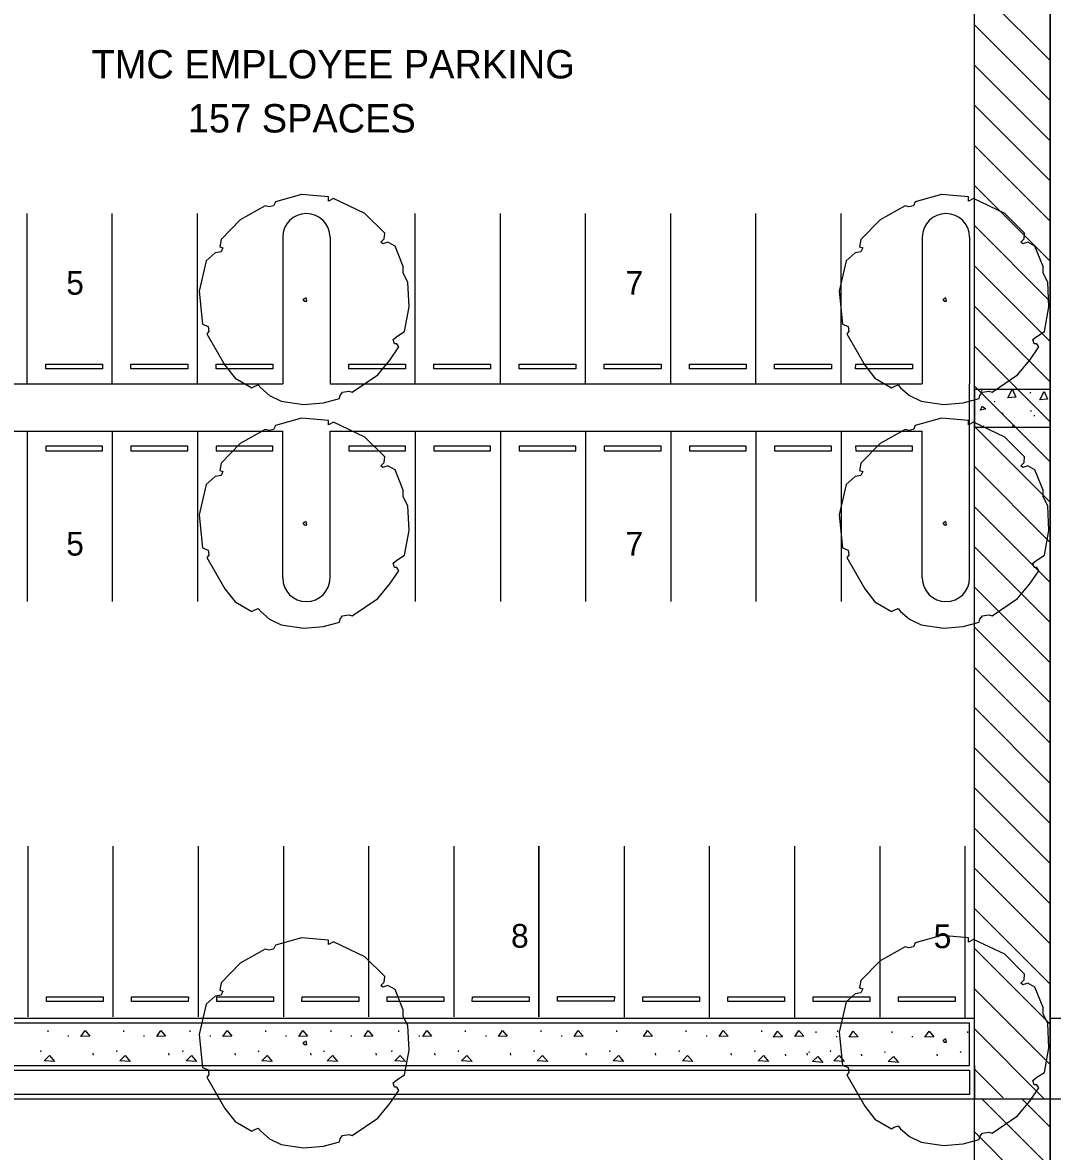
# Model space of a CAD drawing. Extents: x 6712138 to 6712574, y 1869536 to 1870160.
# Drawn here: x 6712370.5 to 6712479.3, y 1869919.6 to 1870038.8 of the extents above; entities that cross this region are included whole.
import ezdxf

# ---------------------------------------------------------------- set-up
doc = ezdxf.new("R2010")
doc.units = 0
for name, color, linetype in [('A-ANNO-TEXT', 7, 'Continuous'), ('A-FLOR-CASE', 7, 'Continuous'), ('A-FLOR-PATT', 7, 'Continuous'), ('A-WALL-MBNI', 7, 'Continuous'), ('C-PRKG-CONC', 7, 'Continuous'), ('C-PRKG-STRP', 7, 'Continuous'), ('L-tree', 7, 'Continuous')]:
    doc.layers.add(name, color=color, linetype=linetype)

# ---------------------------------------------------------------- blocks, each defined once
blk = doc.blocks.new('TREE 1')
at = {"layer": 'L-tree'}
for p, q in [((-0.0275, 0.572), (-0.1682, 0.5324)), ((0.1167, 0.5588), (-0.0275, 0.572)), ((0.1167, 0.5368), (0.1167, 0.5588)), ((0.1441, 0.55), (0.1167, 0.5368)), ((0.3123, 0.4708), (0.1441, 0.55)), ((-0.2231, 0.5104), (-0.357, 0.4356)), ((-0.2025, 0.506), (-0.2231, 0.5104)), ((-0.1785, 0.5104), (-0.2025, 0.506)), ((-0.1682, 0.5324), (-0.1785, 0.5104)), ((-0.357, 0.4356), (-0.4599, 0.33)), ((0.4187, 0.3652), (0.3123, 0.4708)), ((0.4153, 0.3344), (0.4187, 0.3652)), ((-0.4599, 0.33), (-0.4668, 0.2904)), ((0.3981, 0.3168), (0.4153, 0.3344)), ((0.4084, 0.308), (0.3981, 0.3168)), ((0.4359, 0.3168), (0.4084, 0.308)), ((0.4737, 0.2948), (0.4359, 0.3168)), ((-0.4908, 0.2596), (-0.5389, 0.2156)), ((-0.4599, 0.264), (-0.4908, 0.2596)), ((-0.4668, 0.2904), (-0.4496, 0.286)), ((-0.4496, 0.286), (-0.4599, 0.264)), ((0.5183, 0.1848), (0.4737, 0.2948)), ((-0.5389, 0.2156), (-0.5766, 0.0528)), ((0.5183, 0.1496), (0.5183, 0.1848)), ((0.5423, 0.1012), (0.5183, 0.1496)), ((0.5492, -0.0308), (0.5423, 0.1012)), ((-0.5766, 0.0528), (-0.5595, -0.1232)), ((-0.0034, 0.0176), (-0.0206, 0.0088)), ((-0.0206, 0.0088), (-0.0137, 0)), ((-0.0137, 0), (0, 0)), ((0, 0), (-0.0034, 0.0176)), ((0.5251, -0.1628), (0.5492, -0.0308)), ((-0.5595, -0.1232), (-0.5286, -0.1364)), ((-0.5251, -0.1628), (-0.5354, -0.176)), ((-0.5354, -0.176), (-0.4393, -0.3432)), ((-0.5286, -0.1364), (-0.5251, -0.1628)), ((0.4839, -0.1892), (0.5251, -0.1628)), ((0.4634, -0.2068), (0.4839, -0.1892)), ((0.4702, -0.2288), (0.4634, -0.2068)), ((0.4839, -0.2288), (0.4702, -0.2288)), ((0.4942, -0.2464), (0.4839, -0.2288)), ((0.4462, -0.3168), (0.4942, -0.2464)), ((-0.4393, -0.3432), (-0.3844, -0.4136)), ((0.381, -0.396), (0.4462, -0.3168)), ((-0.3844, -0.4136), (-0.2952, -0.4664)), ((0.2437, -0.4884), (0.381, -0.396)), ((-0.2952, -0.4664), (-0.2815, -0.4576)), ((-0.2815, -0.4576), (-0.2609, -0.4488)), ((-0.2609, -0.4488), (-0.2471, -0.4664)), ((-0.2471, -0.4664), (-0.1991, -0.506)), ((0.1922, -0.4884), (0.2265, -0.484)), ((0.2265, -0.484), (0.2437, -0.4884)), ((-0.1991, -0.506), (-0.1373, -0.5368)), ((-0.1373, -0.5368), (-0.0172, -0.5544)), ((0.0892, -0.5456), (0.175, -0.5236)), ((0.175, -0.5236), (0.1785, -0.506)), ((0.1785, -0.506), (0.1922, -0.4884)), ((-0.0172, -0.5544), (0.0892, -0.5456))]:
    blk.add_line(p, q, dxfattribs=at)

msp = doc.modelspace()

# ---------------------------------------------------------------- linework, layer by layer
at = {"layer": 'A-FLOR-CASE'}
msp.add_lwpolyline([(6712471.06, 1869725.57), (6712471.06, 1870137.85), (6712479.06, 1870137.85), (6712479.06, 1869725.57)], close=True, dxfattribs=at)
at = {"layer": 'A-FLOR-PATT'}
for p, q in [((6712471.82, 1869999.86), (6712471.89, 1870000.02)), ((6712476.96, 1869999.68), (6712477.02, 1869999.84)), ((6712473.14, 1869998.89), (6712473.2, 1869998.78)), ((6712473.99, 1869997.6), (6712474.06, 1869997.5)), ((6712476.98, 1869997.88), (6712477.05, 1869997.76)), ((6712477.36, 1869997.38), (6712477.43, 1869997.27)), ((6712471.99, 1869996.12), (6712472.06, 1869996.28)), ((6712477.18, 1869996.07), (6712477.19, 1869996.1)), ((6712373.2, 1869932.21), (6712373.2, 1869932.37)), ((6712375.37, 1869931.74), (6712375.37, 1869931.85)), ((6712381.2, 1869932.21), (6712381.2, 1869932.37)), ((6712383.37, 1869931.74), (6712383.37, 1869931.85)), ((6712388.2, 1869932.21), (6712388.2, 1869932.37)), ((6712390.37, 1869931.74), (6712390.37, 1869931.85)), ((6712396.2, 1869932.21), (6712396.2, 1869932.37)), ((6712398.37, 1869931.74), (6712398.37, 1869931.85)), ((6712403.1, 1869932.21), (6712403.1, 1869932.37)), ((6712405.27, 1869931.74), (6712405.27, 1869931.85)), ((6712410.27, 1869932.21), (6712410.27, 1869932.37)), ((6712412.44, 1869931.74), (6712412.44, 1869931.85)), ((6712417.3, 1869932.21), (6712417.3, 1869932.37)), ((6712419.47, 1869931.74), (6712419.47, 1869931.85)), ((6712425.3, 1869932.21), (6712425.3, 1869932.37)), ((6712427.47, 1869931.74), (6712427.47, 1869931.85)), ((6712433.3, 1869932.21), (6712433.3, 1869932.37)), ((6712440.62, 1869932.21), (6712440.62, 1869932.37)), ((6712442.79, 1869931.74), (6712442.79, 1869931.85)), ((6712448.62, 1869932.21), (6712448.62, 1869932.37)), ((6712450.79, 1869931.74), (6712450.79, 1869931.85)), ((6712454.36, 1869932.11), (6712454.36, 1869932.27)), ((6712456.53, 1869931.64), (6712456.53, 1869931.75)), ((6712456.62, 1869932.21), (6712456.62, 1869932.37)), ((6712462.36, 1869932.11), (6712462.36, 1869932.27)), ((6712464.53, 1869931.64), (6712464.53, 1869931.75)), ((6712470.36, 1869932.11), (6712470.36, 1869932.27)), ((6712372.45, 1869930.12), (6712372.49, 1869930.24)), ((6712378, 1869929.77), (6712377.96, 1869929.97)), ((6712380.45, 1869930.12), (6712380.49, 1869930.24)), ((6712386, 1869929.77), (6712385.96, 1869929.97)), ((6712387.45, 1869930.12), (6712387.49, 1869930.24)), ((6712393, 1869929.77), (6712392.96, 1869929.97)), ((6712395.45, 1869930.12), (6712395.49, 1869930.24)), ((6712401, 1869929.77), (6712400.96, 1869929.97)), ((6712402.35, 1869930.12), (6712402.39, 1869930.24)), ((6712407.9, 1869929.77), (6712407.86, 1869929.97)), ((6712409.52, 1869930.12), (6712409.56, 1869930.24)), ((6712414.1, 1869929.77), (6712414.06, 1869929.97)), ((6712416.55, 1869930.12), (6712416.59, 1869930.24)), ((6712422.1, 1869929.77), (6712422.06, 1869929.97)), ((6712424.55, 1869930.12), (6712424.59, 1869930.24)), ((6712430.1, 1869929.77), (6712430.06, 1869929.97)), ((6712432.55, 1869930.12), (6712432.59, 1869930.24)), ((6712437.42, 1869929.77), (6712437.38, 1869929.97)), ((6712439.87, 1869930.12), (6712439.91, 1869930.24)), ((6712445.42, 1869929.77), (6712445.38, 1869929.97)), ((6712447.87, 1869930.12), (6712447.91, 1869930.24)), ((6712451.16, 1869929.67), (6712451.12, 1869929.87)), ((6712453.42, 1869929.77), (6712453.38, 1869929.97)), ((6712453.61, 1869930.02), (6712453.65, 1869930.14)), ((6712455.87, 1869930.12), (6712455.91, 1869930.24)), ((6712459.16, 1869929.67), (6712459.12, 1869929.87)), ((6712461.61, 1869930.02), (6712461.65, 1869930.14)), ((6712467.16, 1869929.67), (6712467.12, 1869929.87)), ((6712469.61, 1869930.02), (6712469.65, 1869930.14))]:
    msp.add_line(p, q, dxfattribs=at)
for points in [[(6712474.59, 1869999.2), (6712475.05, 1870000.07)], [(6712475.08, 1870000.07), (6712475.43, 1869999.28), (6712474.61, 1869999.2)], [(6712477.96, 1869998.98), (6712478.43, 1869999.88), (6712478.8, 1869999.05), (6712477.98, 1869998.98)], [(6712471.7, 1869997.88), (6712471.9, 1869998.32), (6712472.26, 1869998.05), (6712471.7, 1869997.88)], [(6712475.07, 1869996.07), (6712475.23, 1869996.36), (6712475.36, 1869996.07)], [(6712478.57, 1869996.07), (6712478.6, 1869996.14), (6712478.63, 1869996.07)]]:
    msp.add_lwpolyline(points, dxfattribs=at)
for points in [[(6712376.68, 1869931.74), (6712377.11, 1869932.37), (6712377.62, 1869931.78)], [(6712384.68, 1869931.74), (6712385.11, 1869932.37), (6712385.62, 1869931.78)], [(6712391.68, 1869931.74), (6712392.11, 1869932.37), (6712392.62, 1869931.78)], [(6712399.68, 1869931.74), (6712400.11, 1869932.37), (6712400.62, 1869931.78)], [(6712406.58, 1869931.74), (6712407.01, 1869932.37), (6712407.52, 1869931.78)], [(6712412.78, 1869931.74), (6712413.21, 1869932.37), (6712413.72, 1869931.78)], [(6712420.78, 1869931.74), (6712421.21, 1869932.37), (6712421.72, 1869931.78)], [(6712428.78, 1869931.74), (6712429.21, 1869932.37), (6712429.72, 1869931.78)], [(6712436.1, 1869931.74), (6712436.53, 1869932.37), (6712437.04, 1869931.78)], [(6712444.1, 1869931.74), (6712444.53, 1869932.37), (6712445.04, 1869931.78)], [(6712449.84, 1869931.65), (6712450.27, 1869932.28), (6712450.78, 1869931.69)], [(6712452.1, 1869931.74), (6712452.53, 1869932.37), (6712453.04, 1869931.78)], [(6712457.84, 1869931.65), (6712458.27, 1869932.28), (6712458.78, 1869931.69)], [(6712465.84, 1869931.65), (6712466.27, 1869932.28), (6712466.78, 1869931.69)], [(6712372.79, 1869929.16), (6712373.35, 1869929.71), (6712373.89, 1869929.08)], [(6712380.79, 1869929.16), (6712381.35, 1869929.71), (6712381.89, 1869929.08)], [(6712387.79, 1869929.16), (6712388.35, 1869929.71), (6712388.89, 1869929.08)], [(6712395.79, 1869929.16), (6712396.35, 1869929.71), (6712396.89, 1869929.08)], [(6712402.69, 1869929.16), (6712403.25, 1869929.71), (6712403.79, 1869929.08)], [(6712409.85, 1869929.16), (6712410.41, 1869929.71), (6712410.95, 1869929.08)], [(6712416.89, 1869929.16), (6712417.45, 1869929.71), (6712417.99, 1869929.08)], [(6712424.89, 1869929.16), (6712425.45, 1869929.71), (6712425.99, 1869929.08)], [(6712432.89, 1869929.16), (6712433.45, 1869929.71), (6712433.99, 1869929.08)], [(6712440.21, 1869929.16), (6712440.77, 1869929.71), (6712441.31, 1869929.08)], [(6712448.21, 1869929.16), (6712448.77, 1869929.71), (6712449.31, 1869929.08)], [(6712453.95, 1869929.07), (6712454.51, 1869929.62), (6712455.05, 1869928.99)], [(6712456.21, 1869929.16), (6712456.77, 1869929.71), (6712457.31, 1869929.08)], [(6712461.95, 1869929.07), (6712462.51, 1869929.62), (6712463.05, 1869928.99)]]:
    msp.add_lwpolyline(points, close=True, dxfattribs=at)
at = {"layer": 'A-WALL-MBNI'}
for p, q in [((6712479.06, 1870000.07), (6712471.06, 1870000.07)), ((6712471.06, 1870000.07), (6712471.06, 1869996.07)), ((6712479.06, 1870000.07), (6712479.06, 1869996.07)), ((6712479.06, 1869996.07), (6712471.06, 1869996.07))]:
    msp.add_line(p, q, dxfattribs=at)
at = {"layer": 'C-PRKG-CONC'}
for p, q in [((6712370.99, 1870000.67), (6712370.99, 1870018.67)), ((6712379.99, 1870000.67), (6712379.99, 1870018.67)), ((6712388.99, 1870000.67), (6712388.99, 1870018.67)), ((6712411.99, 1870000.67), (6712411.99, 1870018.67)), ((6712420.99, 1870000.67), (6712420.99, 1870018.67)), ((6712429.99, 1870000.67), (6712429.99, 1870018.67)), ((6712438.99, 1870000.67), (6712438.99, 1870018.67)), ((6712447.99, 1870000.67), (6712447.99, 1870018.67)), ((6712456.99, 1870000.67), (6712456.99, 1870018.67)), ((6712397.99, 1870016.17), (6712397.99, 1870000.67)), ((6712402.99, 1870016.17), (6712402.99, 1870000.67)), ((6712465.56, 1870016.17), (6712465.56, 1870000.67)), ((6712470.56, 1870016.17), (6712470.56, 1870000.67)), ((6712372.96, 1870002.26), (6712372.96, 1870002.76)), ((6712372.96, 1870002.76), (6712378.96, 1870002.76)), ((6712378.96, 1870002.26), (6712372.96, 1870002.26)), ((6712378.96, 1870002.76), (6712378.96, 1870002.26)), ((6712381.96, 1870002.26), (6712381.96, 1870002.76)), ((6712381.96, 1870002.76), (6712387.96, 1870002.76)), ((6712387.96, 1870002.26), (6712381.96, 1870002.26)), ((6712387.96, 1870002.76), (6712387.96, 1870002.26)), ((6712390.96, 1870002.26), (6712390.96, 1870002.76)), ((6712390.96, 1870002.76), (6712396.96, 1870002.76)), ((6712396.96, 1870002.26), (6712390.96, 1870002.26)), ((6712396.96, 1870002.76), (6712396.96, 1870002.26)), ((6712404.96, 1870002.26), (6712404.96, 1870002.76)), ((6712404.96, 1870002.76), (6712410.96, 1870002.76)), ((6712410.96, 1870002.26), (6712404.96, 1870002.26)), ((6712410.96, 1870002.76), (6712410.96, 1870002.26)), ((6712413.96, 1870002.26), (6712413.96, 1870002.76)), ((6712413.96, 1870002.76), (6712419.96, 1870002.76)), ((6712419.96, 1870002.26), (6712413.96, 1870002.26)), ((6712419.96, 1870002.76), (6712419.96, 1870002.26)), ((6712422.96, 1870002.26), (6712422.96, 1870002.76)), ((6712422.96, 1870002.76), (6712428.96, 1870002.76)), ((6712428.96, 1870002.26), (6712422.96, 1870002.26)), ((6712428.96, 1870002.76), (6712428.96, 1870002.26)), ((6712431.96, 1870002.26), (6712431.96, 1870002.76)), ((6712431.96, 1870002.76), (6712437.96, 1870002.76)), ((6712437.96, 1870002.26), (6712431.96, 1870002.26)), ((6712437.96, 1870002.76), (6712437.96, 1870002.26)), ((6712440.96, 1870002.26), (6712440.96, 1870002.76)), ((6712440.96, 1870002.76), (6712446.96, 1870002.76)), ((6712446.96, 1870002.26), (6712440.96, 1870002.26)), ((6712446.96, 1870002.76), (6712446.96, 1870002.26)), ((6712449.96, 1870002.26), (6712449.96, 1870002.76)), ((6712449.96, 1870002.76), (6712455.96, 1870002.76)), ((6712455.96, 1870002.26), (6712449.96, 1870002.26)), ((6712455.96, 1870002.76), (6712455.96, 1870002.26)), ((6712458.52, 1870002.26), (6712458.53, 1870002.76)), ((6712464.52, 1870002.26), (6712458.52, 1870002.26)), ((6712458.53, 1870002.76), (6712464.53, 1870002.76)), ((6712464.53, 1870002.76), (6712464.52, 1870002.26)), ((6712352.99, 1870000.68), (6712397.99, 1870000.67)), ((6712402.99, 1870000.67), (6712465.56, 1870000.67)), ((6712470.56, 1869980.17), (6712470.56, 1870000.67)), ((6712352.99, 1869995.67), (6712397.99, 1869995.67)), ((6712370.99, 1869995.67), (6712370.99, 1869977.67)), ((6712379.99, 1869995.67), (6712379.99, 1869977.67)), ((6712388.99, 1869995.67), (6712388.99, 1869977.67)), ((6712397.99, 1869980.17), (6712397.99, 1869995.67)), ((6712402.99, 1869980.17), (6712402.99, 1869995.67)), ((6712402.99, 1869995.67), (6712465.56, 1869995.67)), ((6712411.99, 1869995.67), (6712411.99, 1869977.67)), ((6712420.99, 1869995.67), (6712420.99, 1869977.67)), ((6712429.99, 1869995.67), (6712429.99, 1869977.67)), ((6712438.99, 1869995.67), (6712438.99, 1869977.67)), ((6712447.99, 1869995.67), (6712447.99, 1869977.67)), ((6712456.99, 1869995.67), (6712456.99, 1869977.67)), ((6712465.56, 1869980.17), (6712465.56, 1869995.67)), ((6712372.96, 1869994.09), (6712372.96, 1869993.59)), ((6712378.96, 1869994.09), (6712372.96, 1869994.09)), ((6712378.96, 1869993.59), (6712378.96, 1869994.09)), ((6712381.96, 1869994.09), (6712381.96, 1869993.59)), ((6712387.96, 1869994.09), (6712381.96, 1869994.09)), ((6712387.96, 1869993.59), (6712387.96, 1869994.09)), ((6712390.96, 1869994.09), (6712390.96, 1869993.59)), ((6712396.96, 1869994.09), (6712390.96, 1869994.09)), ((6712396.96, 1869993.59), (6712396.96, 1869994.09)), ((6712404.96, 1869994.09), (6712404.96, 1869993.59)), ((6712410.96, 1869994.09), (6712404.96, 1869994.09)), ((6712410.96, 1869993.59), (6712410.96, 1869994.09)), ((6712413.96, 1869994.09), (6712413.96, 1869993.59)), ((6712419.96, 1869994.09), (6712413.96, 1869994.09)), ((6712419.96, 1869993.59), (6712419.96, 1869994.09)), ((6712422.96, 1869994.09), (6712422.96, 1869993.59)), ((6712428.96, 1869994.09), (6712422.96, 1869994.09)), ((6712428.96, 1869993.59), (6712428.96, 1869994.09)), ((6712431.96, 1869994.09), (6712431.96, 1869993.59)), ((6712437.96, 1869994.09), (6712431.96, 1869994.09)), ((6712437.96, 1869993.59), (6712437.96, 1869994.09)), ((6712440.96, 1869994.09), (6712440.96, 1869993.59)), ((6712446.96, 1869994.09), (6712440.96, 1869994.09)), ((6712446.96, 1869993.59), (6712446.96, 1869994.09)), ((6712449.96, 1869994.09), (6712449.96, 1869993.59)), ((6712455.96, 1869994.09), (6712449.96, 1869994.09)), ((6712455.96, 1869993.59), (6712455.96, 1869994.09)), ((6712458.52, 1869994.09), (6712458.53, 1869993.59)), ((6712464.52, 1869994.09), (6712458.52, 1869994.09)), ((6712464.53, 1869993.59), (6712464.52, 1869994.09)), ((6712372.96, 1869993.59), (6712378.96, 1869993.59)), ((6712381.96, 1869993.59), (6712387.96, 1869993.59)), ((6712390.96, 1869993.59), (6712396.96, 1869993.59)), ((6712404.96, 1869993.59), (6712410.96, 1869993.59)), ((6712413.96, 1869993.59), (6712419.96, 1869993.59)), ((6712422.96, 1869993.59), (6712428.96, 1869993.59)), ((6712431.96, 1869993.59), (6712437.96, 1869993.59)), ((6712440.96, 1869993.59), (6712446.96, 1869993.59)), ((6712449.96, 1869993.59), (6712455.96, 1869993.59)), ((6712458.53, 1869993.59), (6712464.53, 1869993.59)), ((6712371.06, 1869951.82), (6712371.06, 1869933.82)), ((6712380.06, 1869951.82), (6712380.06, 1869933.82)), ((6712389.06, 1869951.82), (6712389.06, 1869933.82)), ((6712398.06, 1869951.82), (6712398.06, 1869933.82)), ((6712407.06, 1869951.82), (6712407.06, 1869933.82)), ((6712416.06, 1869951.82), (6712416.06, 1869933.82)), ((6712425.06, 1869933.82), (6712425.06, 1869951.82)), ((6712425.06, 1869951.82), (6712425.06, 1869933.82)), ((6712434.06, 1869951.82), (6712434.06, 1869933.77)), ((6712443.06, 1869951.82), (6712443.06, 1869933.77)), ((6712452.06, 1869951.82), (6712452.06, 1869933.77)), ((6712461.06, 1869951.82), (6712461.06, 1869933.77)), ((6712470.06, 1869951.82), (6712470.06, 1869933.67)), ((6712479.06, 1869933.72), (6712479.06, 1869951.72)), ((6712373.02, 1869935.41), (6712373.03, 1869935.91)), ((6712379.02, 1869935.41), (6712373.02, 1869935.41)), ((6712373.03, 1869935.91), (6712379.03, 1869935.91)), ((6712379.03, 1869935.91), (6712379.02, 1869935.41)), ((6712382.02, 1869935.41), (6712382.03, 1869935.91)), ((6712388.02, 1869935.41), (6712382.02, 1869935.41)), ((6712382.03, 1869935.91), (6712388.03, 1869935.91)), ((6712388.03, 1869935.91), (6712388.02, 1869935.41)), ((6712391.02, 1869935.41), (6712391.03, 1869935.91)), ((6712397.02, 1869935.41), (6712391.02, 1869935.41)), ((6712391.03, 1869935.91), (6712397.03, 1869935.91)), ((6712397.03, 1869935.91), (6712397.02, 1869935.41)), ((6712400.02, 1869935.41), (6712400.03, 1869935.91)), ((6712406.02, 1869935.41), (6712400.02, 1869935.41)), ((6712400.03, 1869935.91), (6712406.03, 1869935.91)), ((6712406.03, 1869935.91), (6712406.02, 1869935.41)), ((6712409.02, 1869935.41), (6712409.03, 1869935.91)), ((6712415.02, 1869935.41), (6712409.02, 1869935.41)), ((6712409.03, 1869935.91), (6712415.03, 1869935.91)), ((6712415.03, 1869935.91), (6712415.02, 1869935.41)), ((6712418.02, 1869935.41), (6712418.03, 1869935.91)), ((6712424.02, 1869935.41), (6712418.02, 1869935.41)), ((6712418.03, 1869935.91), (6712424.03, 1869935.91)), ((6712424.03, 1869935.91), (6712424.02, 1869935.41)), ((6712427.02, 1869935.46), (6712427.03, 1869935.96)), ((6712433.02, 1869935.46), (6712427.02, 1869935.46)), ((6712427.03, 1869935.96), (6712433.03, 1869935.96)), ((6712433.03, 1869935.96), (6712433.02, 1869935.46)), ((6712436.02, 1869935.41), (6712436.03, 1869935.91)), ((6712442.02, 1869935.41), (6712436.02, 1869935.41)), ((6712436.03, 1869935.91), (6712442.03, 1869935.91)), ((6712442.03, 1869935.91), (6712442.02, 1869935.41)), ((6712242.06, 1869933.67), (6712471.06, 1869933.67)), ((6712242.06, 1869933.17), (6712470.56, 1869933.17)), ((6712470.56, 1869928.67), (6712470.56, 1869933.17)), ((6712479.06, 1869933.67), (6712516.06, 1869933.67)), ((6712241.56, 1869928.17), (6712470.56, 1869928.17)), ((6712242.06, 1869928.67), (6712470.56, 1869928.67)), ((6712470.56, 1869928.17), (6712470.56, 1869925.61)), ((6712471.06, 1869928.67), (6712471.06, 1869925.11)), ((6712479.06, 1869928.67), (6712479.06, 1869925.11)), ((6712470.56, 1869925.61), (6712235.54, 1869925.61)), ((6712471.06, 1869925.11), (6712235.54, 1869925.11)), ((6712521.68, 1869925.11), (6712479.06, 1869925.11))]:
    msp.add_line(p, q, dxfattribs=at)
for points in [[(6712445.03, 1869935.91), (6712451.02, 1869935.91), (6712451.02, 1869935.41), (6712445.03, 1869935.41)], [(6712454.03, 1869935.91), (6712460.02, 1869935.91), (6712460.02, 1869935.41), (6712454.03, 1869935.41)], [(6712463.03, 1869935.91), (6712469.02, 1869935.91), (6712469.02, 1869935.41), (6712463.03, 1869935.41)]]:
    msp.add_lwpolyline(points, close=True, dxfattribs=at)
for centre, start, end in [((6712400.49, 1870016.17), 0, 180), ((6712468.06, 1870016.17), 0, 180), ((6712400.49, 1869980.17), 180, 360), ((6712468.06, 1869980.17), 180, 360)]:
    msp.add_arc(centre, 2.5, start, end, dxfattribs=at)
at = {"layer": 'C-PRKG-STRP'}
for p, q in [((6712471.06, 1869890.59), (6712471.06, 1870137.85)), ((6712479.06, 1869890.59), (6712479.06, 1870137.85)), ((6712479.06, 1870034.84), (6712471.06, 1870042.84)), ((6712479.06, 1870030.6), (6712471.06, 1870038.6)), ((6712479.06, 1870026.36), (6712471.06, 1870034.36)), ((6712479.06, 1870022.11), (6712471.06, 1870030.11)), ((6712479.06, 1870017.87), (6712471.06, 1870025.87)), ((6712479.06, 1870013.63), (6712471.06, 1870021.63)), ((6712479.06, 1870009.39), (6712471.06, 1870017.39)), ((6712479.06, 1870005.14), (6712471.06, 1870013.14)), ((6712479.06, 1870000.9), (6712471.06, 1870008.9)), ((6712479.06, 1869996.66), (6712471.06, 1870004.66)), ((6712479.06, 1869992.42), (6712471.06, 1870000.42)), ((6712479.06, 1869988.17), (6712471.06, 1869996.17)), ((6712479.06, 1869983.93), (6712471.06, 1869991.93)), ((6712479.06, 1869979.69), (6712471.06, 1869987.69)), ((6712479.06, 1869975.45), (6712471.06, 1869983.45)), ((6712479.06, 1869971.2), (6712471.06, 1869979.2)), ((6712479.06, 1869966.96), (6712471.06, 1869974.96)), ((6712479.06, 1869962.72), (6712471.06, 1869970.72)), ((6712479.06, 1869958.47), (6712471.06, 1869966.47)), ((6712479.06, 1869954.23), (6712471.06, 1869962.23)), ((6712479.06, 1869949.99), (6712471.06, 1869957.99)), ((6712479.06, 1869945.75), (6712471.06, 1869953.75)), ((6712479.06, 1869941.5), (6712471.06, 1869949.5)), ((6712479.06, 1869937.26), (6712471.06, 1869945.26)), ((6712479.06, 1869933.02), (6712471.06, 1869941.02)), ((6712479.06, 1869928.78), (6712471.06, 1869936.78)), ((6712478.4, 1869925.19), (6712471.06, 1869932.53)), ((6712474.1, 1869925.25), (6712471.06, 1869928.29)), ((6712479.06, 1869925.11), (6712471.06, 1869925.11)), ((6712479.06, 1869917.92), (6712471.87, 1869925.11)), ((6712479.06, 1869922.16), (6712476.11, 1869925.11)), ((6712479.06, 1869913.67), (6712471.06, 1869921.67))]:
    msp.add_line(p, q, dxfattribs=at)

# ---------------------------------------------------------------- block references
at = {"layer": 'L-tree', "xscale": 19.68503937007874, "yscale": 19.68503937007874}
for p in [(6712400.53, 1870009.42), (6712468.13, 1870009.42), (6712400.53, 1869985.79), (6712468.13, 1869985.79), (6712468.13, 1869931.14), (6712400.53, 1869930.89)]:
    msp.add_blockref('TREE 1', p, dxfattribs=at)

# ---------------------------------------------------------------- texts
at = {"layer": 'A-ANNO-TEXT'}
for s, p in [('TMC EMPLOYEE PARKING', (6712377.8, 1870032.94)), ('157 SPACES', (6712387.97, 1870027.23))]:
    msp.add_text(s, height=3, dxfattribs=at).set_placement(p)
for s, p in [('5', (6712375.13, 1870010.09)), ('7', (6712434.22, 1870010.09)), ('5', (6712375.13, 1869982.53)), ('7', (6712434.22, 1869982.53)), ('8', (6712422.12, 1869941.11)), ('5', (6712466.77, 1869941.06))]:
    msp.add_text(s, height=2.5, rotation=0.2528, dxfattribs=at).set_placement(p)

doc.saveas('drawing.dxf')
